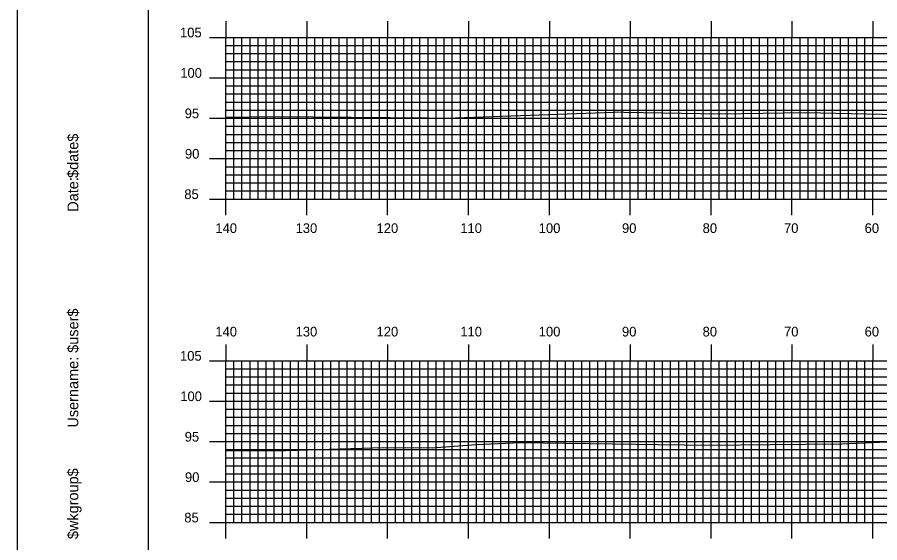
# Model space of a CAD drawing. Extents: x 1778319 to 1778662, y 442591 to 442811.
# Drawn here: x 1778318.5 to 1778425.2, y 442686.2 to 442751.2 of the extents above; entities that cross this region are included whole.
import ezdxf

# ---------------------------------------------------------------- set-up
doc = ezdxf.new("R2010")
doc.units = 0
for name, color, linetype in [('BORDER', 7, 'Continuous'), ('H_V ANNOTATION', 7, 'Continuous'), ('MAJOR', 7, 'Continuous'), ('MINOR', 7, 'Continuous'), ('PLOT BOUNDARY', 7, 'Continuous'), ('S_Roadway_Centerline', 7, 'Continuous')]:
    doc.layers.add(name, color=color, linetype=linetype)

msp = doc.modelspace()

# ---------------------------------------------------------------- linework, layer by layer
at = {"layer": 'BORDER'}
msp.add_lwpolyline([(1778334.7, 442596.67), (1778654.7, 442596.67), (1778654.7, 442806.67), (1778334.7, 442806.67)], close=True, dxfattribs=at)
at = {"layer": 'MAJOR'}
for p, q in [((1778344.3, 442750.67), (1778344.3, 442748.67)), ((1778354.3, 442750.67), (1778354.3, 442748.67)), ((1778364.3, 442750.67), (1778364.3, 442748.67)), ((1778374.3, 442750.67), (1778374.3, 442748.67)), ((1778384.3, 442750.67), (1778384.3, 442748.67)), ((1778394.3, 442750.67), (1778394.3, 442748.67)), ((1778404.3, 442750.67), (1778404.3, 442748.67)), ((1778414.3, 442750.67), (1778414.3, 442748.67)), ((1778424.3, 442750.67), (1778424.3, 442748.67)), ((1778342.3, 442748.67), (1778344.3, 442748.67)), ((1778344.3, 442748.67), (1778624.3, 442748.67)), ((1778344.3, 442728.67), (1778344.3, 442748.67)), ((1778344.3, 442728.67), (1778344.3, 442748.67)), ((1778344.3, 442748.67), (1778624.3, 442748.67)), ((1778354.3, 442728.67), (1778354.3, 442748.67)), ((1778364.3, 442728.67), (1778364.3, 442748.67)), ((1778374.3, 442728.67), (1778374.3, 442748.67)), ((1778384.3, 442728.67), (1778384.3, 442748.67)), ((1778394.3, 442728.67), (1778394.3, 442748.67)), ((1778404.3, 442728.67), (1778404.3, 442748.67)), ((1778414.3, 442728.67), (1778414.3, 442748.67)), ((1778424.3, 442728.67), (1778424.3, 442748.67)), ((1778342.3, 442743.67), (1778344.3, 442743.67)), ((1778344.3, 442743.67), (1778624.3, 442743.67)), ((1778342.3, 442738.67), (1778344.3, 442738.67)), ((1778344.3, 442738.67), (1778624.3, 442738.67)), ((1778342.3, 442733.67), (1778344.3, 442733.67)), ((1778344.3, 442733.67), (1778624.3, 442733.67)), ((1778342.3, 442728.67), (1778344.3, 442728.67)), ((1778344.3, 442728.67), (1778624.3, 442728.67)), ((1778344.3, 442728.67), (1778624.3, 442728.67)), ((1778344.3, 442726.66), (1778344.3, 442728.67)), ((1778354.3, 442726.66), (1778354.3, 442728.67)), ((1778364.3, 442726.66), (1778364.3, 442728.67)), ((1778374.3, 442726.66), (1778374.3, 442728.67)), ((1778384.3, 442726.66), (1778384.3, 442728.67)), ((1778394.3, 442726.66), (1778394.3, 442728.67)), ((1778404.3, 442726.66), (1778404.3, 442728.67)), ((1778414.3, 442726.66), (1778414.3, 442728.67)), ((1778424.3, 442726.66), (1778424.3, 442728.67)), ((1778344.3, 442710.67), (1778344.3, 442708.67)), ((1778354.3, 442710.67), (1778354.3, 442708.67)), ((1778364.3, 442710.67), (1778364.3, 442708.67)), ((1778374.3, 442710.67), (1778374.3, 442708.67)), ((1778384.3, 442710.67), (1778384.3, 442708.67)), ((1778394.3, 442710.67), (1778394.3, 442708.67)), ((1778404.3, 442710.67), (1778404.3, 442708.67)), ((1778414.3, 442710.67), (1778414.3, 442708.67)), ((1778424.3, 442710.67), (1778424.3, 442708.67)), ((1778342.3, 442708.67), (1778344.3, 442708.67)), ((1778344.3, 442708.67), (1778624.3, 442708.67)), ((1778344.3, 442688.67), (1778344.3, 442708.67)), ((1778344.3, 442688.67), (1778344.3, 442708.67)), ((1778344.3, 442708.67), (1778624.3, 442708.67)), ((1778354.3, 442688.67), (1778354.3, 442708.67)), ((1778364.3, 442688.67), (1778364.3, 442708.67)), ((1778374.3, 442688.67), (1778374.3, 442708.67)), ((1778384.3, 442688.67), (1778384.3, 442708.67)), ((1778394.3, 442688.67), (1778394.3, 442708.67)), ((1778404.3, 442688.67), (1778404.3, 442708.67)), ((1778414.3, 442688.67), (1778414.3, 442708.67)), ((1778424.3, 442688.67), (1778424.3, 442708.67)), ((1778342.3, 442703.67), (1778344.3, 442703.67)), ((1778344.3, 442703.67), (1778624.3, 442703.67)), ((1778342.3, 442698.67), (1778344.3, 442698.67)), ((1778344.3, 442698.67), (1778624.3, 442698.67)), ((1778342.3, 442693.67), (1778344.3, 442693.67)), ((1778344.3, 442693.67), (1778624.3, 442693.67)), ((1778342.3, 442688.67), (1778344.3, 442688.67)), ((1778344.3, 442688.67), (1778624.3, 442688.67)), ((1778344.3, 442688.67), (1778624.3, 442688.67)), ((1778344.3, 442686.66), (1778344.3, 442688.67)), ((1778354.3, 442686.66), (1778354.3, 442688.67)), ((1778364.3, 442686.66), (1778364.3, 442688.67)), ((1778374.3, 442686.66), (1778374.3, 442688.67)), ((1778384.3, 442686.66), (1778384.3, 442688.67)), ((1778394.3, 442686.66), (1778394.3, 442688.67)), ((1778404.3, 442686.66), (1778404.3, 442688.67)), ((1778414.3, 442686.66), (1778414.3, 442688.67)), ((1778424.3, 442686.66), (1778424.3, 442688.67))]:
    msp.add_line(p, q, dxfattribs=at)
at = {"layer": 'MINOR'}
for p, q in [((1778345.3, 442728.67), (1778345.3, 442748.67)), ((1778346.3, 442728.67), (1778346.3, 442748.67)), ((1778347.3, 442728.67), (1778347.3, 442748.67)), ((1778348.3, 442728.67), (1778348.3, 442748.67)), ((1778349.3, 442728.67), (1778349.3, 442748.67)), ((1778350.3, 442728.67), (1778350.3, 442748.67)), ((1778351.3, 442728.67), (1778351.3, 442748.67)), ((1778352.3, 442728.67), (1778352.3, 442748.67)), ((1778353.3, 442728.67), (1778353.3, 442748.67)), ((1778355.3, 442728.67), (1778355.3, 442748.67)), ((1778356.3, 442728.67), (1778356.3, 442748.67)), ((1778357.3, 442728.67), (1778357.3, 442748.67)), ((1778358.3, 442728.67), (1778358.3, 442748.67)), ((1778359.3, 442728.67), (1778359.3, 442748.67)), ((1778360.3, 442728.67), (1778360.3, 442748.67)), ((1778361.3, 442728.67), (1778361.3, 442748.67)), ((1778362.3, 442728.67), (1778362.3, 442748.67)), ((1778363.3, 442728.67), (1778363.3, 442748.67)), ((1778365.3, 442728.67), (1778365.3, 442748.67)), ((1778366.3, 442728.67), (1778366.3, 442748.67)), ((1778367.3, 442728.67), (1778367.3, 442748.67)), ((1778368.3, 442728.67), (1778368.3, 442748.67)), ((1778369.3, 442728.67), (1778369.3, 442748.67)), ((1778370.3, 442728.67), (1778370.3, 442748.67)), ((1778371.3, 442728.67), (1778371.3, 442748.67)), ((1778372.3, 442728.67), (1778372.3, 442748.67)), ((1778373.3, 442728.67), (1778373.3, 442748.67)), ((1778375.3, 442728.67), (1778375.3, 442748.67)), ((1778376.3, 442728.67), (1778376.3, 442748.67)), ((1778377.3, 442728.67), (1778377.3, 442748.67)), ((1778378.3, 442728.67), (1778378.3, 442748.67)), ((1778379.3, 442728.67), (1778379.3, 442748.67)), ((1778380.3, 442728.67), (1778380.3, 442748.67)), ((1778381.3, 442728.67), (1778381.3, 442748.67)), ((1778382.3, 442728.67), (1778382.3, 442748.67)), ((1778383.3, 442728.67), (1778383.3, 442748.67)), ((1778385.3, 442728.67), (1778385.3, 442748.67)), ((1778386.3, 442728.67), (1778386.3, 442748.67)), ((1778387.3, 442728.67), (1778387.3, 442748.67)), ((1778388.3, 442728.67), (1778388.3, 442748.67)), ((1778389.3, 442728.67), (1778389.3, 442748.67)), ((1778390.3, 442728.67), (1778390.3, 442748.67)), ((1778391.3, 442728.67), (1778391.3, 442748.67)), ((1778392.3, 442728.67), (1778392.3, 442748.67)), ((1778393.3, 442728.67), (1778393.3, 442748.67)), ((1778395.3, 442728.67), (1778395.3, 442748.67)), ((1778396.3, 442728.67), (1778396.3, 442748.67)), ((1778397.3, 442728.67), (1778397.3, 442748.67)), ((1778398.3, 442728.67), (1778398.3, 442748.67)), ((1778399.3, 442728.67), (1778399.3, 442748.67)), ((1778400.3, 442728.67), (1778400.3, 442748.67)), ((1778401.3, 442728.67), (1778401.3, 442748.67)), ((1778402.3, 442728.67), (1778402.3, 442748.67)), ((1778403.3, 442728.67), (1778403.3, 442748.67)), ((1778405.3, 442728.67), (1778405.3, 442748.67)), ((1778406.3, 442728.67), (1778406.3, 442748.67)), ((1778407.3, 442728.67), (1778407.3, 442748.67)), ((1778408.3, 442728.67), (1778408.3, 442748.67)), ((1778409.3, 442728.67), (1778409.3, 442748.67)), ((1778410.3, 442728.67), (1778410.3, 442748.67)), ((1778411.3, 442728.67), (1778411.3, 442748.67)), ((1778412.3, 442728.67), (1778412.3, 442748.67)), ((1778413.3, 442728.67), (1778413.3, 442748.67)), ((1778415.3, 442728.67), (1778415.3, 442748.67)), ((1778416.3, 442728.67), (1778416.3, 442748.67)), ((1778417.3, 442728.67), (1778417.3, 442748.67)), ((1778418.3, 442728.67), (1778418.3, 442748.67)), ((1778419.3, 442728.67), (1778419.3, 442748.67)), ((1778420.3, 442728.67), (1778420.3, 442748.67)), ((1778421.3, 442728.67), (1778421.3, 442748.67)), ((1778422.3, 442728.67), (1778422.3, 442748.67)), ((1778423.3, 442728.67), (1778423.3, 442748.67)), ((1778344.3, 442747.67), (1778624.3, 442747.67)), ((1778344.3, 442747.67), (1778346.31, 442747.67)), ((1778344.3, 442746.67), (1778624.3, 442746.67)), ((1778344.3, 442746.67), (1778346.31, 442746.67)), ((1778344.3, 442745.67), (1778624.3, 442745.67)), ((1778344.3, 442745.67), (1778346.31, 442745.67)), ((1778344.3, 442744.67), (1778624.3, 442744.67)), ((1778344.3, 442744.67), (1778346.31, 442744.67)), ((1778344.3, 442742.67), (1778624.3, 442742.67)), ((1778344.3, 442742.67), (1778346.31, 442742.67)), ((1778344.3, 442741.67), (1778624.3, 442741.67)), ((1778344.3, 442741.67), (1778346.31, 442741.67)), ((1778344.3, 442740.67), (1778624.3, 442740.67)), ((1778344.3, 442740.67), (1778346.31, 442740.67)), ((1778344.3, 442739.67), (1778624.3, 442739.67)), ((1778344.3, 442739.67), (1778346.31, 442739.67)), ((1778344.3, 442737.67), (1778624.3, 442737.67)), ((1778344.3, 442737.67), (1778346.31, 442737.67)), ((1778344.3, 442736.67), (1778624.3, 442736.67)), ((1778344.3, 442736.67), (1778346.31, 442736.67)), ((1778344.3, 442735.67), (1778624.3, 442735.67)), ((1778344.3, 442735.67), (1778346.31, 442735.67)), ((1778344.3, 442734.67), (1778624.3, 442734.67)), ((1778344.3, 442734.67), (1778346.31, 442734.67)), ((1778344.3, 442732.67), (1778624.3, 442732.67)), ((1778344.3, 442732.67), (1778346.31, 442732.67)), ((1778344.3, 442731.67), (1778624.3, 442731.67)), ((1778344.3, 442731.67), (1778346.31, 442731.67)), ((1778344.3, 442730.67), (1778624.3, 442730.67)), ((1778344.3, 442730.67), (1778346.31, 442730.67)), ((1778344.3, 442729.67), (1778624.3, 442729.67)), ((1778344.3, 442729.67), (1778346.31, 442729.67)), ((1778345.3, 442688.67), (1778345.3, 442708.67)), ((1778346.3, 442688.67), (1778346.3, 442708.67)), ((1778347.3, 442688.67), (1778347.3, 442708.67)), ((1778348.3, 442688.67), (1778348.3, 442708.67)), ((1778349.3, 442688.67), (1778349.3, 442708.67)), ((1778350.3, 442688.67), (1778350.3, 442708.67)), ((1778351.3, 442688.67), (1778351.3, 442708.67)), ((1778352.3, 442688.67), (1778352.3, 442708.67)), ((1778353.3, 442688.67), (1778353.3, 442708.67)), ((1778355.3, 442688.67), (1778355.3, 442708.67)), ((1778356.3, 442688.67), (1778356.3, 442708.67)), ((1778357.3, 442688.67), (1778357.3, 442708.67)), ((1778358.3, 442688.67), (1778358.3, 442708.67)), ((1778359.3, 442688.67), (1778359.3, 442708.67)), ((1778360.3, 442688.67), (1778360.3, 442708.67)), ((1778361.3, 442688.67), (1778361.3, 442708.67)), ((1778362.3, 442688.67), (1778362.3, 442708.67)), ((1778363.3, 442688.67), (1778363.3, 442708.67)), ((1778365.3, 442688.67), (1778365.3, 442708.67)), ((1778366.3, 442688.67), (1778366.3, 442708.67)), ((1778367.3, 442688.67), (1778367.3, 442708.67)), ((1778368.3, 442688.67), (1778368.3, 442708.67)), ((1778369.3, 442688.67), (1778369.3, 442708.67)), ((1778370.3, 442688.67), (1778370.3, 442708.67)), ((1778371.3, 442688.67), (1778371.3, 442708.67)), ((1778372.3, 442688.67), (1778372.3, 442708.67)), ((1778373.3, 442688.67), (1778373.3, 442708.67)), ((1778375.3, 442688.67), (1778375.3, 442708.67)), ((1778376.3, 442688.67), (1778376.3, 442708.67)), ((1778377.3, 442688.67), (1778377.3, 442708.67)), ((1778378.3, 442688.67), (1778378.3, 442708.67)), ((1778379.3, 442688.67), (1778379.3, 442708.67)), ((1778380.3, 442688.67), (1778380.3, 442708.67)), ((1778381.3, 442688.67), (1778381.3, 442708.67)), ((1778382.3, 442688.67), (1778382.3, 442708.67)), ((1778383.3, 442688.67), (1778383.3, 442708.67)), ((1778385.3, 442688.67), (1778385.3, 442708.67)), ((1778386.3, 442688.67), (1778386.3, 442708.67)), ((1778387.3, 442688.67), (1778387.3, 442708.67)), ((1778388.3, 442688.67), (1778388.3, 442708.67)), ((1778389.3, 442688.67), (1778389.3, 442708.67)), ((1778390.3, 442688.67), (1778390.3, 442708.67)), ((1778391.3, 442688.67), (1778391.3, 442708.67)), ((1778392.3, 442688.67), (1778392.3, 442708.67)), ((1778393.3, 442688.67), (1778393.3, 442708.67)), ((1778395.3, 442688.67), (1778395.3, 442708.67)), ((1778396.3, 442688.67), (1778396.3, 442708.67)), ((1778397.3, 442688.67), (1778397.3, 442708.67)), ((1778398.3, 442688.67), (1778398.3, 442708.67)), ((1778399.3, 442688.67), (1778399.3, 442708.67)), ((1778400.3, 442688.67), (1778400.3, 442708.67)), ((1778401.3, 442688.67), (1778401.3, 442708.67)), ((1778402.3, 442688.67), (1778402.3, 442708.67)), ((1778403.3, 442688.67), (1778403.3, 442708.67)), ((1778405.3, 442688.67), (1778405.3, 442708.67)), ((1778406.3, 442688.67), (1778406.3, 442708.67)), ((1778407.3, 442688.67), (1778407.3, 442708.67)), ((1778408.3, 442688.67), (1778408.3, 442708.67)), ((1778409.3, 442688.67), (1778409.3, 442708.67)), ((1778410.3, 442688.67), (1778410.3, 442708.67)), ((1778411.3, 442688.67), (1778411.3, 442708.67)), ((1778412.3, 442688.67), (1778412.3, 442708.67)), ((1778413.3, 442688.67), (1778413.3, 442708.67)), ((1778415.3, 442688.67), (1778415.3, 442708.67)), ((1778416.3, 442688.67), (1778416.3, 442708.67)), ((1778417.3, 442688.67), (1778417.3, 442708.67)), ((1778418.3, 442688.67), (1778418.3, 442708.67)), ((1778419.3, 442688.67), (1778419.3, 442708.67)), ((1778420.3, 442688.67), (1778420.3, 442708.67)), ((1778421.3, 442688.67), (1778421.3, 442708.67)), ((1778422.3, 442688.67), (1778422.3, 442708.67)), ((1778423.3, 442688.67), (1778423.3, 442708.67)), ((1778344.3, 442707.67), (1778624.3, 442707.67)), ((1778344.3, 442707.67), (1778346.31, 442707.67)), ((1778344.3, 442706.67), (1778624.3, 442706.67)), ((1778344.3, 442706.67), (1778346.31, 442706.67)), ((1778344.3, 442705.67), (1778624.3, 442705.67)), ((1778344.3, 442705.67), (1778346.31, 442705.67)), ((1778344.3, 442704.67), (1778624.3, 442704.67)), ((1778344.3, 442704.67), (1778346.31, 442704.67)), ((1778344.3, 442702.67), (1778624.3, 442702.67)), ((1778344.3, 442702.67), (1778346.31, 442702.67)), ((1778344.3, 442701.67), (1778624.3, 442701.67)), ((1778344.3, 442701.67), (1778346.31, 442701.67)), ((1778344.3, 442700.67), (1778624.3, 442700.67)), ((1778344.3, 442700.67), (1778346.31, 442700.67)), ((1778344.3, 442699.67), (1778624.3, 442699.67)), ((1778344.3, 442699.67), (1778346.31, 442699.67)), ((1778344.3, 442697.67), (1778624.3, 442697.67)), ((1778344.3, 442697.67), (1778346.31, 442697.67)), ((1778344.3, 442696.67), (1778624.3, 442696.67)), ((1778344.3, 442696.67), (1778346.31, 442696.67)), ((1778344.3, 442695.67), (1778624.3, 442695.67)), ((1778344.3, 442695.67), (1778346.31, 442695.67)), ((1778344.3, 442694.67), (1778624.3, 442694.67)), ((1778344.3, 442694.67), (1778346.31, 442694.67)), ((1778344.3, 442692.67), (1778624.3, 442692.67)), ((1778344.3, 442692.67), (1778346.31, 442692.67)), ((1778344.3, 442691.67), (1778624.3, 442691.67)), ((1778344.3, 442691.67), (1778346.31, 442691.67)), ((1778344.3, 442690.67), (1778624.3, 442690.67)), ((1778344.3, 442690.67), (1778346.31, 442690.67)), ((1778344.3, 442689.67), (1778624.3, 442689.67)), ((1778344.3, 442689.67), (1778346.31, 442689.67))]:
    msp.add_line(p, q, dxfattribs=at)
at = {"layer": 'PLOT BOUNDARY'}
msp.add_lwpolyline([(1778318.52, 442590.55), (1778658.52, 442590.55), (1778658.52, 442810.55), (1778318.52, 442810.55)], close=True, dxfattribs=at)
at = {"layer": 'S_Roadway_Centerline'}
for points in [[(1778344.3, 442738.77), (1778344.36, 442738.78), (1778350.34, 442738.87), (1778369.31, 442738.72), (1778370.87, 442738.69), (1778372.67, 442738.71), (1778392.29, 442739.41), (1778392.91, 442739.44), (1778393.49, 442739.43), (1778405.38, 442739.22), (1778416.01, 442739.36), (1778417.84, 442739.35), (1778429.26, 442739.09)], [(1778344.3, 442697.54), (1778351.74, 442697.56), (1778363.81, 442697.94), (1778369.8, 442697.91), (1778375.27, 442698.29), (1778380.71, 442698.55), (1778397.81, 442698.31), (1778404.22, 442698.22), (1778411.59, 442698.3), (1778420.47, 442698.41), (1778434.49, 442699.01), (1778443.08, 442699.04), (1778449.53, 442698.61), (1778457.77, 442698.57), (1778464.69, 442698.54), (1778480.82, 442698.56), (1778487.72, 442698.62), (1778505.5, 442698.92), (1778508.12, 442698.95), (1778512.92, 442698.95), (1778532.18, 442699)]]:
    msp.add_lwpolyline(points, dxfattribs=at)

# ---------------------------------------------------------------- texts
at = {"layer": 'BORDER'}
for s, p in [('$date$', (1778326.07, 442731.28)), ('Date:', (1778326.07, 442727.1)), ('$user$', (1778326.07, 442709.65)), ('Username:', (1778326.07, 442700.4)), ('$wkgroup$', (1778326.07, 442686.6))]:
    msp.add_text(s, height=1.339, rotation=90, dxfattribs=at).set_placement(p)
at = {"layer": 'H_V ANNOTATION'}
for s, p in [('105', (1778338.64, 442748.67)), ('100', (1778338.67, 442743.67)), ('95', (1778339.22, 442738.67)), ('90', (1778339.25, 442733.67)), ('85', (1778339.17, 442728.67)), ('140', (1778343.01, 442724.47)), ('130', (1778352.93, 442724.47)), ('120', (1778362.94, 442724.47)), ('110', (1778373.29, 442724.47)), ('100', (1778382.99, 442724.47)), ('90', (1778393.28, 442724.47)), ('80', (1778403.25, 442724.47)), ('70', (1778413.31, 442724.47)), ('60', (1778423.28, 442724.47)), ('140', (1778343.01, 442711.67)), ('130', (1778352.93, 442711.67)), ('120', (1778362.94, 442711.67)), ('110', (1778373.29, 442711.67)), ('100', (1778382.99, 442711.67)), ('90', (1778393.28, 442711.67)), ('80', (1778403.25, 442711.67)), ('70', (1778413.31, 442711.67)), ('60', (1778423.28, 442711.67)), ('105', (1778338.64, 442708.67)), ('100', (1778338.67, 442703.67)), ('95', (1778339.22, 442698.67)), ('90', (1778339.25, 442693.67)), ('85', (1778339.17, 442688.67))]:
    msp.add_text(s, height=1.2, dxfattribs=at).set_placement(p)
at = {"layer": 'MAJOR'}
for p in [(1778344.29, 442728.67), (1778344.29, 442688.67)]:
    msp.add_text('-', height=0.012, dxfattribs=at).set_placement(p)

doc.saveas('drawing.dxf')
